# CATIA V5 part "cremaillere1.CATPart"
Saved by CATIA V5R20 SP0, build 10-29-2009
Part number: cremaillere_1
Definition: NONE
Nomenclature: 1
Source: Unknown
Description: PART-1-DESC
Bounding box of the stored display mesh (mm): x 0 to 45, y -4.7 to 6, z -2 to 2
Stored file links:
  F:\Catia_finish\cremaillere1.CATPart
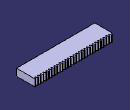
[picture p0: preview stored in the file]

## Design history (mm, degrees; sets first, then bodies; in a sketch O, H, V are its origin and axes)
Set1
  Sketch1 on xy-plane, origin (0, 0, 0), H (1, 0, 0), V (0, 1, 0)
    line L1 (45, 40) -> (298, 40)
    line L2 (298, 40) -> (298, -31)
    line L3 (298, -31) -> (45, -31)
    line L4 (45, -31) -> (45, 40)
    distance L4 V = 45
    horizontal: L1 H, L3 H
    vertical: L2 V, L4 V
Body1 "1" (main body)
  Solid1: solid without history
  Pocket1: profile Sketch1, direction (0, 0, -1), length 20, opposite side length 20
  Pad1: profile face of Solid1, direction along edge [face of Pocket1 from Sketch1.L4 | face of Solid1], length 4.7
